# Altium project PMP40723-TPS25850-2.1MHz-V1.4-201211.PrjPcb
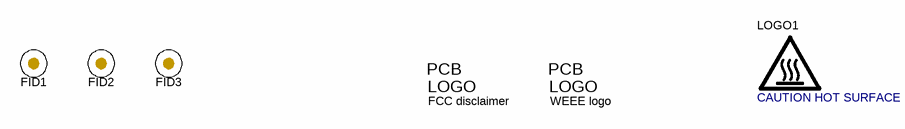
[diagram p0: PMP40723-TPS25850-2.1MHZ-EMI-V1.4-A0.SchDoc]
CopyrightYear: 2020; PCB_Layout: Pioneer Li; PCB_Rev: E1; PRJ_Customer: Public Release; PRJ_Engineer: Pioneer Li; PRJ_Number: PMP40723; PRJ_Title: Change in menu Project|Project Options|Parameters; SCH_Rev: E1; TechSupport: http://www.ti.com/support; TID: N/A
2 sheets, 79 parts. Net scope: global (net labels, ports and power ports of the same name join across sheets).
Board file: PMP40723-TPS25850-2.1MHZ-EMI-V1.4-A1.PcbDoc
Sheets:
  PMP40723-TPS25850-2.1MHZ-EMI-V1.4-A0.SchDoc
  PMP40723-TPS25850-2.1MHZ-EMI-V1.4-A1.SchDoc

## Sheet PMP40723-TPS25850-2.1MHZ-EMI-V1.4-A0.SchDoc
size 431 x 279 mm; Date: Not shown in title block; ApprovedBy: Not shown in title block; CheckedBy: Not shown in title block; Author: Not shown in title block; CompanyName: Not shown in title block; Engineer: Not shown in title block; Organization: Not shown in title block; Address1: Not shown in title block; Address2: Not shown in title block; Address3: Not shown in title block; Address4: Not shown in title block; DocumentNumber: 3; Revision: Use project parameter SCH_Rev; SheetNumber: 3; SheetTotal: 3; PageSetup: Record=PageOptions¦CenterHorizontal=True¦CenterVertical=True¦PrintScale=1.00¦XCorrection=1.00¦YCorrection=1.00¦PrintKind=0¦BorderSize=5000000¦LeftOffset=0¦BottomOffset=0¦Orientation=2¦PaperLength=1000¦PaperWidth=1000¦Scale=100¦PaperSource=15¦PrintQuality=600¦MediaType=1¦DitherType=10¦PaperKind=Letter¦PrintScaleMode=1

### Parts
FID1  Fiducial  [Fiducial10-20]  (value not drawn)
FID2  Fiducial  [Fiducial10-20]  (value not drawn)
FID3  Fiducial  [Fiducial10-20]  (value not drawn)
LOGO1  CAUTION HOT SURFACE  [IEC_HotSurface_Small]  (no BOM)
Logo3  FCC disclaimer  [FCC_disclaimer]  (no BOM)
Logo4  WEEE logo  [WEEE_Minimum]  (no BOM)

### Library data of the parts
FID1-FID3 = CMP-0077181-1: Fiducial mark.  There is nothing to buy or mount.
LOGO1 = CMP-0074837-1: IEC 61010-1 Hot Surface Warning; SymbolCreator: a0412235
Logo3 = CMP-0074847-1: FCC_disclaimer; Library Reference: Logo
Logo4 = CMP-0074769-1

## Sheet PMP40723-TPS25850-2.1MHZ-EMI-V1.4-A1.SchDoc
size 431 x 279 mm; Date: Not shown in title block; ApprovedBy: Not shown in title block; CheckedBy: Not shown in title block; Author: Not shown in title block; CompanyName: Not shown in title block; Engineer: Not shown in title block; Organization: Not shown in title block; Address1: Not shown in title block; Address2: Not shown in title block; Address3: Not shown in title block; Address4: Not shown in title block; DocumentNumber: 2; Revision: Use project parameter SCH_Rev; SheetNumber: 2; SheetTotal: 3; PageSetup: Record=PageOptions¦CenterHorizontal=True¦CenterVertical=True¦PrintScale=1.00¦XCorrection=1.00¦YCorrection=1.00¦PrintKind=0¦BorderSize=5000000¦LeftOffset=0¦BottomOffset=0¦Orientation=2¦PaperLength=1000¦PaperWidth=1000¦Scale=100¦PaperSource=15¦PrintQuality=600¦MediaType=1¦DitherType=10¦PaperKind=Letter¦PrintScaleMode=1
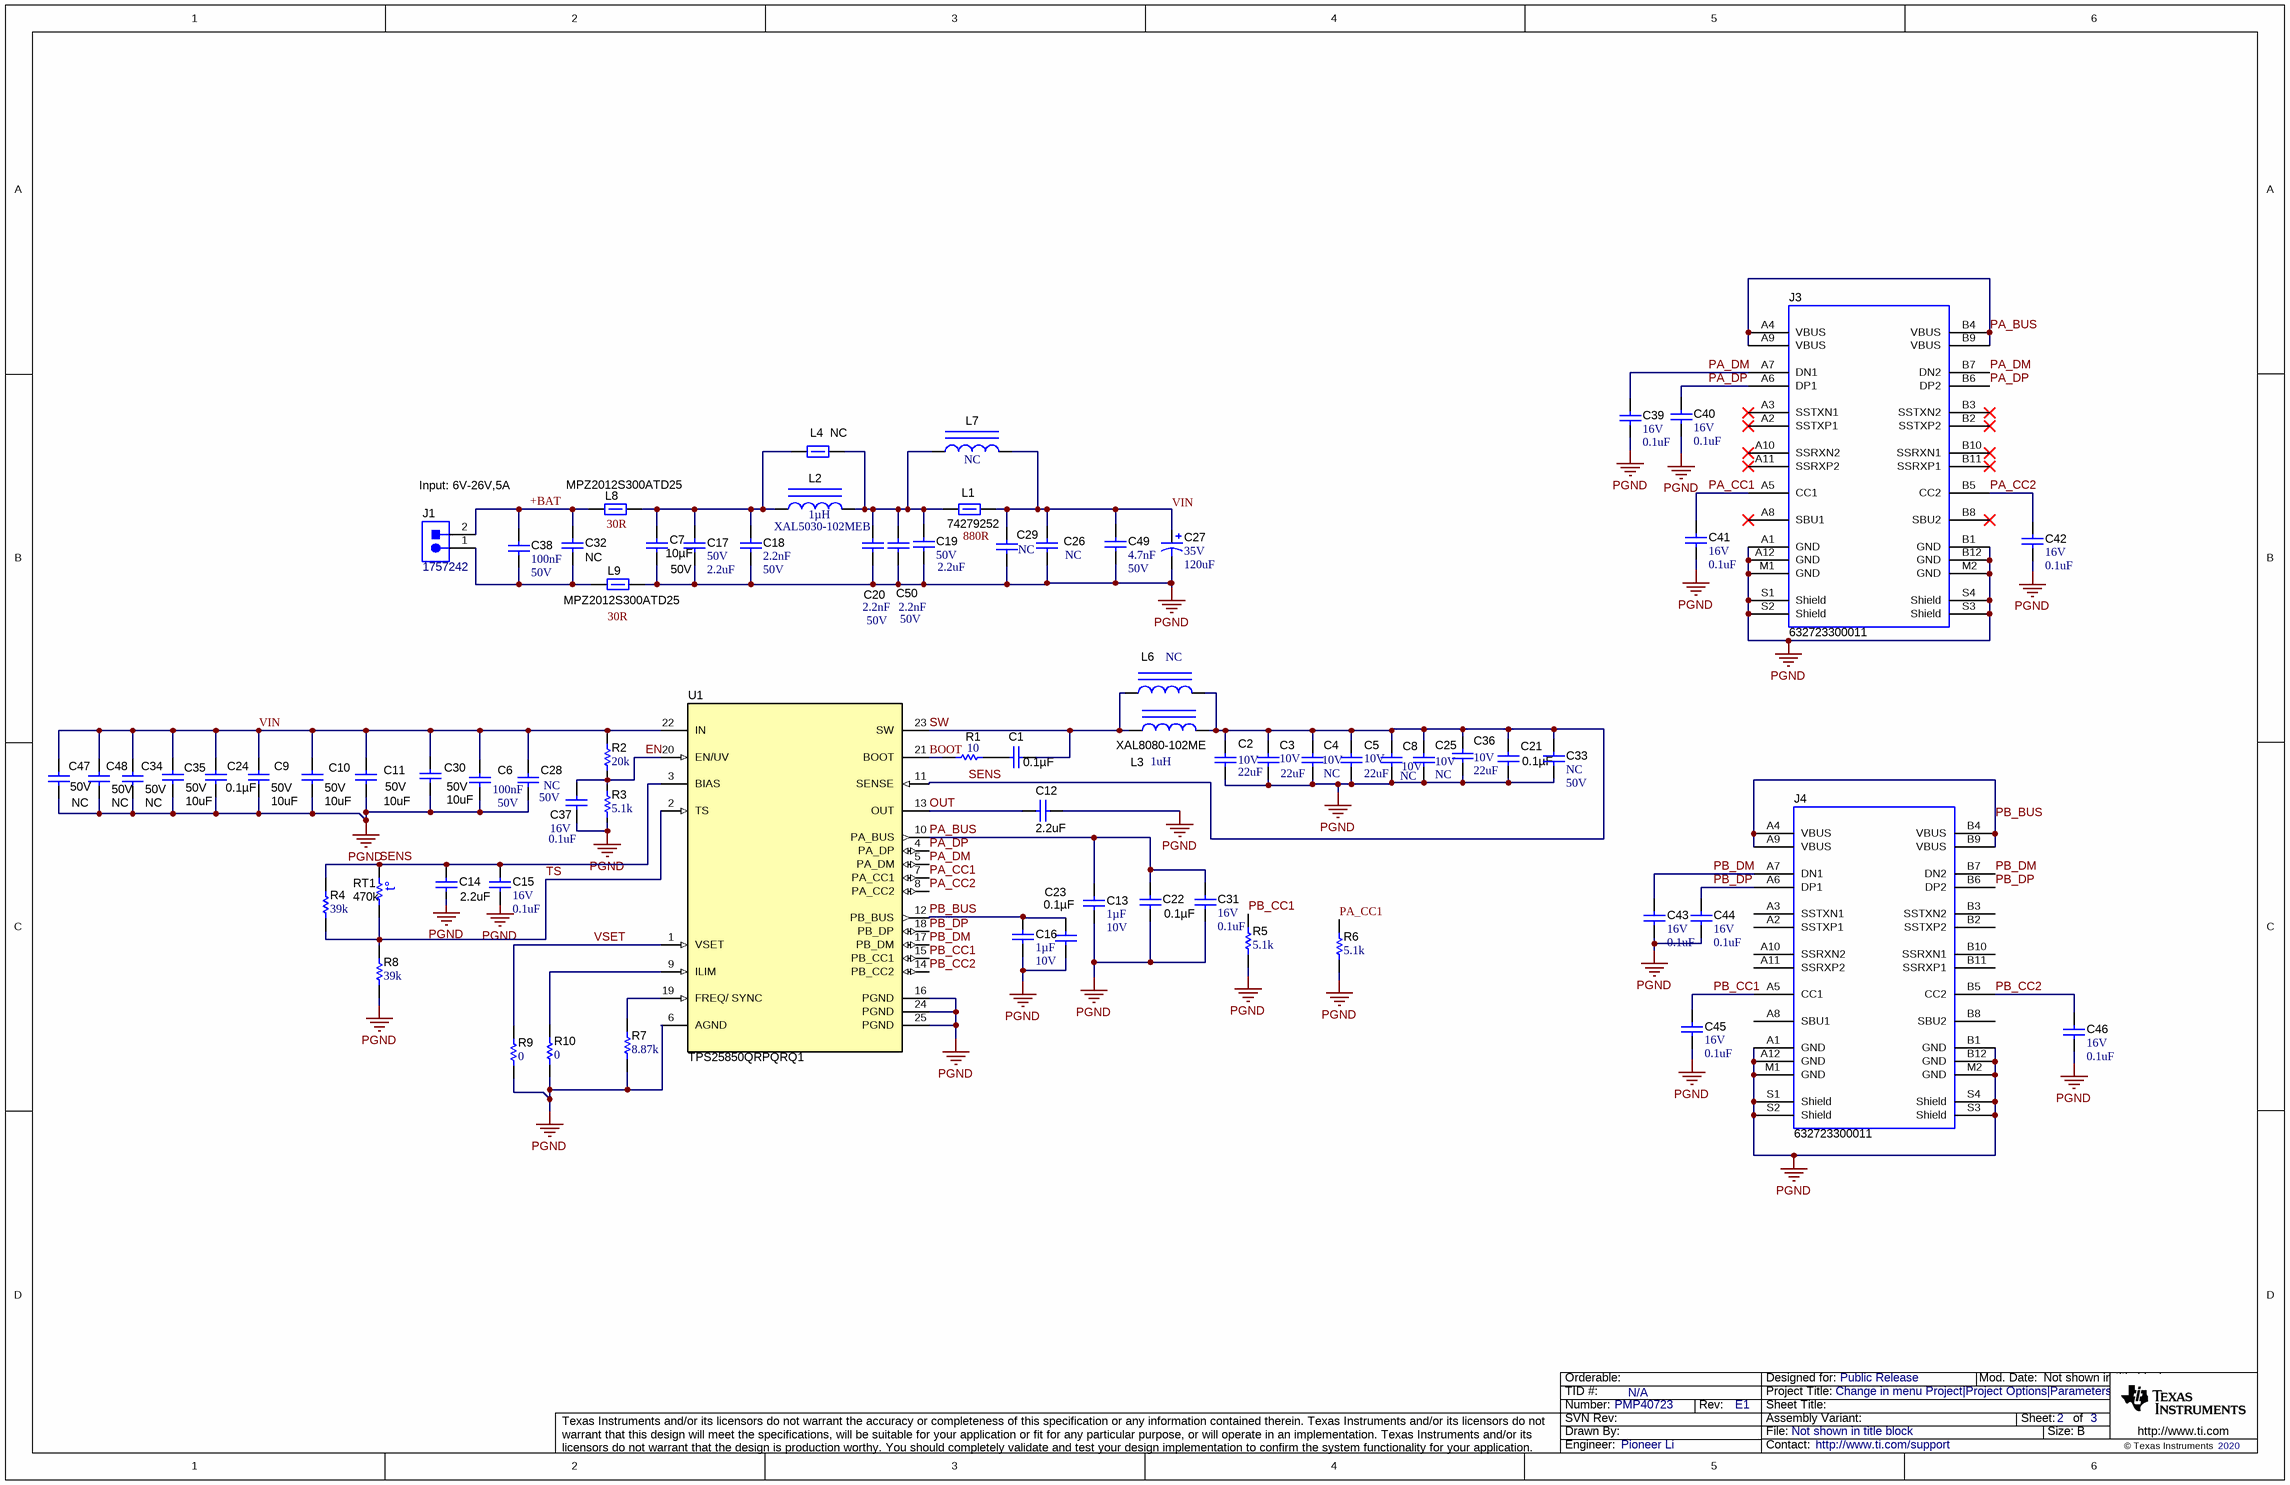
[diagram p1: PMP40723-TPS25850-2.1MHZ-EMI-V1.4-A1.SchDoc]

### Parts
C1  ValueDisplayed: 0.1µF  [0603]  (hidden comment: C0603C104K5RACAUTO)
C2  VDC_V: 10V  ValueDisplayed: 22uF  [1206_180]  (hidden comment: GRM31CR71A226ME15L)
C3  VDC_V: 10V  ValueDisplayed: 22uF  [1206_180]  (hidden comment: GRM31CR71A226ME15L)
C4  VDC_V: 10V  ValueDisplayed: NC  [1206_180]  (hidden comment: GRM31CR71A226ME15L)
C5  VDC_V: 10V  ValueDisplayed: 22uF  [1206_180]  (hidden comment: GRM31CR71A226ME15L)
C6  Cap_F: 100nF  VDC_V: 50V  [0805_HV]  (hidden comment: CL21B104MBCNNNC)
C7  ValueDisplayed: 10µF  VDC_V: 50V  [1206_190]  (hidden comment: CGA5L1X7R1H106K160AC)
C8  VDC_V: 10V  ValueDisplayed: NC  [1206_180]  (hidden comment: GRM31CR71A226ME15L)
C9  VDC_V: 50V  ValueDisplayed: 10uF  [1206_180]  (hidden comment: GRT31CR61H106KE01L)
C10  VDC_V: 50V  ValueDisplayed: 10uF  [1206_180]  (hidden comment: GRT31CR61H106KE01L)
C11  VDC_V: 50V  ValueDisplayed: 10uF  [1206_180]  (hidden comment: GRT31CR61H106KE01L)
C12  ValueDisplayed: 2.2uF  [0603]  (hidden comment: 885012106018)
C13  Cap_F: 1µF  VDC_V: 10V  [0805_HV]  (hidden comment: C2012X7R1A106M125AC)
C14  ValueDisplayed: 2.2uF  [0603]  (hidden comment: 885012106018)
C15  VDC_V: 16V  ValueDisplayed: 0.1uF  [0402]  (hidden comment: GRM155R71C104JA88D)
C16  Cap_F: 1µF  VDC_V: 10V  [0805_HV]  (hidden comment: C2012X7R1A106M125AC)
C17  VDC_V: 50V  ValueDisplayed: 2.2uF  [1206_180]  (hidden comment: GCM31CR71H225KA55L)
C18  Cap_F: 2.2nF  VDC_V: 50V  [0603]  (hidden comment: C0603C222K5RACTU)
C19  VDC_V: 50V  ValueDisplayed: 2.2uF  [1206_180]  (hidden comment: GCM31CR71H225KA55L)
C20  Cap_F: 2.2nF  VDC_V: 50V  [0603]  (hidden comment: C0603C222K5RACTU)
C21  ValueDisplayed: 0.1µF  [0603]  (hidden comment: C0603C104K5RACAUTO)
C22  ValueDisplayed: 0.1µF  [0603]  (hidden comment: C0603C104K5RACAUTO)
C23  ValueDisplayed: 0.1µF  [0603]  (hidden comment: C0603C104K5RACAUTO)
C24  ValueDisplayed: 0.1µF  [0603]  (hidden comment: C0603C104K5RACAUTO)
C25  VDC_V: 10V  ValueDisplayed: NC  [1206_180]  (hidden comment: GRM31CR71A226ME15L)
C26  ValueDisplayed: NC  [1206_190]  (hidden comment: CGA5L3X7R1H475K160AE)
C27  VDC_V: 35V  ValueDisplayed: 120uF  [SM_RADIAL_D8]  (hidden comment: EEHZKV121XUP)
C28  Cap_F: NC  VDC_V: 50V  [0805_HV]  (hidden comment: CL21B104MBCNNNC)
C29  GRM188R71H332KA01D  [0603]  (value not drawn)
C30  VDC_V: 50V  ValueDisplayed: 10uF  [1206_180]  (hidden comment: GRT31CR61H106KE01L)
C31  VDC_V: 16V  ValueDisplayed: 0.1uF  [0402]  (hidden comment: GRM155R71C104JA88D)
C32  ValueDisplayed: NC  [0603]  (hidden comment: C0603C104K5RACAUTO)
C33  Cap_F: NC  VDC_V: 50V  [0603]  (hidden comment: C0603X222K5RACTU)
C34  VDC_V: 50V  ValueDisplayed: NC  [1206_180]  (hidden comment: GRT31CR61H106KE01L)
C35  VDC_V: 50V  ValueDisplayed: 10uF  [1206_180]  (hidden comment: GRT31CR61H106KE01L)
C36  VDC_V: 10V  ValueDisplayed: 22uF  [1206_180]  (hidden comment: GRM31CR71A226ME15L)
C37  VDC_V: 16V  ValueDisplayed: 0.1uF  [0402]  (hidden comment: C0402C104K4RACAUTO)
C38  Cap_F: 100nF  VDC_V: 50V  [0805_150]  (hidden comment: CEU4J2X7R1H104K125AE)
C39  VDC_V: 16V  ValueDisplayed: 0.1uF  [0402]  (hidden comment: GRM155R71C104JA88D)
C40  VDC_V: 16V  ValueDisplayed: 0.1uF  [0402]  (hidden comment: GRM155R71C104JA88D)
C41  VDC_V: 16V  ValueDisplayed: 0.1uF  [0402]  (hidden comment: GRM155R71C104JA88D)
C42  VDC_V: 16V  ValueDisplayed: 0.1uF  [0402]  (hidden comment: GRM155R71C104JA88D)
C43  VDC_V: 16V  ValueDisplayed: 0.1uF  [0402]  (hidden comment: GRM155R71C104JA88D)
C44  VDC_V: 16V  ValueDisplayed: 0.1uF  [0402]  (hidden comment: GRM155R71C104JA88D)
C45  VDC_V: 16V  ValueDisplayed: 0.1uF  [0402]  (hidden comment: GRM155R71C104JA88D)
C46  VDC_V: 16V  ValueDisplayed: 0.1uF  [0402]  (hidden comment: GRM155R71C104JA88D)
C47  VDC_V: 50V  ValueDisplayed: NC  [1206_180]  (hidden comment: GRT31CR61H106KE01L)
C48  VDC_V: 50V  ValueDisplayed: NC  [1206_180]  (hidden comment: GRT31CR61H106KE01L)
C49  Cap_F: 4.7nF  VDC_V: 50V  [0603]  (hidden comment: GCM188R71H472KA37D)
C50  Cap_F: 2.2nF  VDC_V: 50V  [0603]  (hidden comment: C0603C222K5RACTU)
J1  1757242  [PHOENIX_1757242]
J3  632723300011  [Wurth_632_723_300_011]
J4  632723300011  [Wurth_632_723_300_011]
L1  74279252  [1812_170_HighSpeed]
L2  ValueDisplayed: 1µH  [XAL5030]  (hidden comment: XAL5030-102MEB)
L3  XAL8080-102ME  ValueDisplayed: NC  [XAL8080]
L4  NC  [1812_170_HighSpeed]
L6  ValueDisplayed: 1uH  [XAL6060]  (hidden comment: XAL6060-472MEB)
L7  PartNumber: NC  [XAL5030]  (hidden comment: XAL5030-102MEB)
L8  MPZ2012S300ATD25  [1206]
L9  MPZ2012S300ATD25  [1206]
R1  ValueDisplayed: 10  [0603]  (hidden comment: CRCW060310R0JNEA)
R2  ValueDisplayed: 20k  [0402]  (hidden comment: CRCW040220K0JNED)
R3  ValueDisplayed: 5.1k  [0402]  (hidden comment: CRCW04025K10JNED)
R4  ValueDisplayed: 39k  [0402]  (hidden comment: ERJ-2GEJ393X)
R5  ValueDisplayed: 5.1k  [0402]  (hidden comment: CRCW04025K10JNED)
R6  ValueDisplayed: 5.1k  [0402]  (hidden comment: CRCW04025K10JNED)
R7  ValueDisplayed: 8.87k  [0402]  (hidden comment: CRCW04028K87FKED)
R8  ValueDisplayed: 39k  [0402]  (hidden comment: ERJ-2GEJ393X)
R9  ValueDisplayed: 0  [0402]  (hidden comment: MCR01MZPJ000)
R10  ValueDisplayed: 0  [0402]  (hidden comment: MCR01MZPJ000)
RT1  value 470k  [0603S]  (hidden comment: NCP18WM474J03RB)
U1  TPS25850QRPQRQ1  [RPQ0025A]

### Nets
PGND: C2.2 C3.2 C4.2 C5.2 C6.2 C7.2 C8.2 C9.2 C10.2 C11.2 C12.2 C13.2 C14.2 C15.2 C16.2 C17.2 C18.2 C19.2 C20.2 C21.2 C22.2 C23.2 C24.2 C25.2 C26.2 C27.2(-) C28.2 C29.2 C30.2 C31.2 C33.2 C34.2 C35.2 C36.2 C37.2 C39.2 C40.2 C41.2 C42.2 C43.2 C44.2 C45.2 C46.2 C47.2 C48.2 C49.2 C50.2 J3.A1(GND) J3.A12(GND) J3.B1(GND) J3.B12(GND) J3.M1(GND) J3.M2(GND) J3.S1(Shield) J3.S2(Shield) J3.S3(Shield) J3.S4(Shield) J4.A1(GND) J4.A12(GND) J4.B1(GND) J4.B12(GND) J4.M1(GND) J4.M2(GND) J4.S1(Shield) J4.S2(Shield) J4.S3(Shield) J4.S4(Shield) L9.2 R3.1 R5.1 R6.1 R7.1 R8.1 R9.1 R10.1 U1.6(AGND) U1.16(PGND) U1.24(PGND) U1.25(PGND)
+BAT: C32.1 C38.1 J1.2 L8.1
BOOT: R1.1 U1.21(BOOT)
EN: C37.1 R2.1 R3.2 U1.20(EN/UV)
OUT: C12.1 U1.13(OUT)
PA_BUS: C13.1 C22.1 C31.1 J3.A4(VBUS) J3.A9(VBUS) J3.B4(VBUS) J3.B9(VBUS) U1.10(PA_BUS)
PA_CC1: C41.1 J3.A5(CC1) R6.2 U1.7(PA_CC1)
PA_CC2: C42.1 J3.B5(CC2) U1.8(PA_CC2)
PA_DM: C39.1 J3.A7(DN1) J3.B7(DN2) U1.5(PA_DM)
PA_DP: C40.1 J3.A6(DP1) J3.B6(DP2) U1.4(PA_DP)
PB_BUS: C16.1 C23.1 J4.A4(VBUS) J4.A9(VBUS) J4.B4(VBUS) J4.B9(VBUS) U1.12(PB_BUS)
PB_CC1: C45.1 J4.A5(CC1) R5.2 U1.15(PB_CC1)
PB_CC2: C46.1 J4.B5(CC2) U1.14(PB_CC2)
PB_DM: C43.1 J4.A7(DN1) J4.B7(DN2) U1.17(PB_DM)
PB_DP: C44.1 J4.A6(DP1) J4.B6(DP2) U1.18(PB_DP)
SENS: C2.1 C3.1 C4.1 C5.1 C8.1 C14.1 C15.1 C21.1 C25.1 C33.1 C36.1 L3.2 L6.2 R4.2 RT1.2 U1.3(BIAS) U1.11(SENSE)
SW: C1.1 L3.1 L6.1 U1.23(SW)
TS: R4.1 R8.2 RT1.1 U1.2(TS)
VIN: C6.1 C9.1 C10.1 C11.1 C24.1 C26.1 C27.1(+) C28.1 C29.1 C30.1 C34.1 C35.1 C47.1 C48.1 C49.1 L1.2 L7.2 R2.2 U1.22(IN)
VSET: R9.2 U1.1(VSET)
NetC1_2: C1.2 R1.2
NetC7_1: C7.1 C17.1 C18.1 L2.1 L4.1 L8.2
NetC19_1: C19.1 C20.1 C50.1 L1.1 L2.2 L4.2 L7.1
NetC32_2: C32.2 C38.2 J1.1 L9.1
NetR7_2: R7.2 U1.19(FREQ/_SYNC)
NetR10_2: R10.2 U1.9(ILIM)

Not connected (* = marked no-connect by the designer): J3 A2(SSTXP1)* A3(SSTXN1)* A8(SBU1)* A10(SSRXN2)* A11(SSRXP2)* B2(SSTXP2)* B3(SSTXN2)* B8(SBU2)* B10(SSRXN1)* B11(SSRXP1)*; J4 A2(SSTXP1) A3(SSTXN1) A8(SBU1) A10(SSRXN2) A11(SSRXP2) B2(SSTXP2) B3(SSTXN2) B8(SBU2) B10(SSRXN1) B11(SSRXP1)

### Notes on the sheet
- Input: 6V-26V,5A
- Labels drawn without touching a wire or pin: 30R, 880R, FREQ, ILIM

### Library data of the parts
C1 C21-C24 C32 = CMP-0079602-1: CAP, CERM, 0.1 µF, 50 V,+/- 10%, X7R, AEC-Q200 Grade 1, 0603; Manufacturer: Kemet; TaMin_C: -55°C; Polarized: N; SizeAreaWB_mm2: 4.68; U/M: EA; Value: 0.1uF; TaMax_C: 125°C; SizeZ_mm: 1; SizeX_mm: 1.6; SizeY_mm: 0.8; Value2: 50V; SizeArea_mm2: 1.28; CompType: Capacitor; AEC Qualified: Y; Cap_F: 100nF; AEC Category: Q200
C2-C5 C8 C25 C36 = CMP-0008960-2: CAP, CERM, 22 uF, 10 V, +/- 20%, X7R, 1206; Manufacturer: MuRata; TaMin_C: -55°C; Polarized: N; SizeAreaWB_mm2: 10.92; Value1: Unknown; U/M: EA; Value: 22uF; TaMax_C: 125°C; SizeZ_mm: 1.8; SizeX_mm: 3.2; SizeY_mm: 1.6; Cap_Case: 1206; SizeArea_mm2: 5.12; Cap_F: 22µF; AEC Category: Q200
C6 C28 = CMP-0082524-1: CAP, CERM, 0.1 µF, 50 V,+/- 20%, X7R, 0805; Manufacturer: Samsung; SizeAreaWB_mm2: 6.75; SizeArea_mm2: 2.5; AEC Qualified: N; AEC Category: Q200; Value: 0.1uF; TaMax_C: 125°C; SizeZ_mm: 1.45; TaMin_C: -55°C; SizeY_mm: 1.25; U/M: EA; SizeX_mm: 2; Cap_Case: 0805; ValueDisplayed: 0.1µF
C7 = CMP-0085950-1: CAP, CERM, 10 µF, 50 V,+/- 10%, X7R, AEC-Q200 Grade 1, 1206; Manufacturer: TDK; SizeZ_mm: 1.9; Value: 10uF; Cap_Case: 1206; AEC Grade: 1; TaMin_C: -55°C; U/M: EA; SizeArea_mm2: 5.12; TaMax_C: 125°C; AEC Qualified: Y; AEC Category: Q200; SizeX_mm: 3.2; SizeY_mm: 1.6; Polarized: N; SizeAreaWB_mm2: 10.92
C9-C11 C30 C34 C35 C47 C48 = CMP-0009015-1: CAP, CERM, 10 uF, 50 V, +/- 10%, X5R, AEC-Q200 Grade 1, 1206; Manufacturer: MuRata; TaMin_C: -55°C; Polarized: N; SizeAreaWB_mm2: 10.92; Value1: Unknown; U/M: EA; Value: 10uF; TaMax_C: 85°C; SizeZ_mm: 1.8; SizeX_mm: 3.2; SizeY_mm: 1.6; Cap_Case: 1206; SizeArea_mm2: 5.12; AEC Qualified: Y; Cap_F: 10µF; AEC Grade: 1; AEC Category: Q200
C12 C14 = CMP-0006825-5: CAP, CERM, 2.2 uF, 16 V, +/- 20%, X5R, 0603; Manufacturer: Wurth Elektronik; TaMin_C: -55°C; Polarized: N; SizeAreaWB_mm2: 4.68; Value1: Unknown; U/M: EA; Value: 2.2uF; TaMax_C: 85°C; SizeZ_mm: 1; SizeX_mm: 1.6; SizeY_mm: 0.8; Value2: 16V; SizeArea_mm2: 1.28; CompType: Capacitor; Cap_F: 2.2µF; AEC Category: Q200
C13 C16 = CMP-0007864-2: CAP, CERM, 10 uF, 10 V, +/- 20%, X7R, 0805; Manufacturer: TDK; TaMin_C: -55°C; Polarized: N; SizeAreaWB_mm2: 6.75; Value1: Unknown; U/M: EA; Value: 10uF; TaMax_C: 125°C; SizeZ_mm: 1.45; SizeX_mm: 2; SizeY_mm: 1.25; Cap_Case: 0805; SizeArea_mm2: 2.5; AEC Category: Q200
C15 C31 C39-C46 = CMP-0006640-2: CAP, CERM, 0.1 uF, 16 V, +/- 5%, X7R, 0402; Manufacturer: MuRata; TaMin_C: -55°C; Polarized: N; SizeAreaWB_mm2: 3; Value1: Unknown; U/M: EA; Value: 0.1uF; TaMax_C: 125°C; SizeZ_mm: 0.6; SizeX_mm: 1; SizeY_mm: 0.5; Cap_F: 100nF; AEC Category: Q200
C17 C19 = CMP-0008814-2: CAP, CERM, 2.2 uF, 50 V, +/- 10%, X7R, AEC-Q200 Grade 1, 1206; Manufacturer: MuRata; TaMin_C: -55°C; Polarized: N; SizeAreaWB_mm2: 10.92; Value1: Unknown; U/M: EA; Value: 2.2uF; TaMax_C: 125°C; SizeZ_mm: 1.8; SizeX_mm: 3.2; SizeY_mm: 1.6; Cap_Case: 1206; SizeArea_mm2: 5.12; AEC Qualified: Y; Cap_F: 2.2µF; AEC Grade: 1; AEC Category: Q200
C18 C20 C50 = CMP-0006898-4: CAP, CERM, 2200 pF, 50 V, +/- 10%, X7R, 0603; Manufacturer: Kemet; TaMin_C: -55°C; Polarized: N; SizeAreaWB_mm2: 4.68; Value1: Unknown; U/M: EA; Value: 2200pF; TaMax_C: 125°C; SizeZ_mm: 1; SizeX_mm: 1.6; SizeY_mm: 0.8; SizeArea_mm2: 1.28; AEC Category: Q200
C26 = CMP-0085349-1: CAP, CERM, 4.7 µF, 50 V,+/- 10%, X7R, AEC-Q200 Grade 1, 1206; Manufacturer: TDK; Cap_Case: 1206; Value2: 50V; AEC Category: Q200; SizeY_mm: 1.6; TaMin_C: -55°C; TaMax_C: 125°C; U/M: EA; AEC Qualified: Y; SizeAreaWB_mm2: 10.92; Cap_F: 4.7µF; AEC Grade: 1; SizeZ_mm: 1.9; SizeArea_mm2: 5.12; Value: 4.7uF; Polarized: N; SizeX_mm: 3.2
C27 = CMP-0010724-1: CAP, AL, 120 uF, 35 V, +/- 20%, 0.035 ohm, AEC-Q200 , SMD; Manufacturer: Panasonic; TaMin_C: -55°C; ESR_ohm: 0.035; Polarized: Y; SizeAreaWB_mm2: 84.28; Value: 120uF; TaMax_C: 125°C; SizeZ_mm: 7.7; SizeX_mm: 7.8; SizeY_mm: 6.6; Cap_Case: D8; SizeArea_mm2: 51.48; CompType: Capacitor; IRMS_A: 1.7A; AEC Category: Q200
C29 = CMP-0007450-4: CAP, CERM, 3300 pF, 50 V, +/- 10%, X7R, 0603; Manufacturer: MuRata; TaMin_C: -55°C; Polarized: N; SizeAreaWB_mm2: 4.68; Value1: Unknown; U/M: EA; Value: 3300pF; TaMax_C: 125°C; SizeZ_mm: 1; SizeX_mm: 1.6; SizeY_mm: 0.8; Value2: 50V; SizeArea_mm2: 1.28; Cap_F: 3.3nF; AEC Category: Q200
C33 = CMP-0006983-4: CAP, CERM, 2200 pF, 50 V, +/- 10%, X7R, 0603; Manufacturer: Kemet; TaMin_C: -55°C; Polarized: N; SizeAreaWB_mm2: 4.68; Value1: Unknown; U/M: EA; Value: 2200pF; TaMax_C: 125°C; SizeZ_mm: 1; SizeX_mm: 1.6; SizeY_mm: 0.8; SizeArea_mm2: 1.28; AEC Category: Q200
C37 = CMP-0006237-2: CAP, CERM, 0.1 uF, 16 V, +/- 10%, X7R, AEC-Q200 Grade 1, 0402; Manufacturer: Kemet; TaMin_C: -55°C; Polarized: N; SizeAreaWB_mm2: 3; Value1: Unknown; U/M: EA; Value: 0.1uF; TaMax_C: 125°C; SizeZ_mm: 0.6; SizeX_mm: 1; SizeY_mm: 0.5; AEC Qualified: Y; Cap_F: 100nF; AEC Category: Q200
C38 = CMP-0007961-2: CAP, CERM, 0.1 uF, 50 V, +/- 10%, X7R, AEC-Q200 Grade 1, 0805; Manufacturer: TDK; TaMin_C: -55°C; Polarized: N; SizeAreaWB_mm2: 6.75; Value1: Unknown; U/M: EA; Value: 0.1uF; TaMax_C: 125°C; SizeZ_mm: 1.5; SizeX_mm: 2; SizeY_mm: 1.25; Cap_Case: 0805; SizeArea_mm2: 2.5; AEC Qualified: Y; AEC Grade: 1; AEC Category: Q200
C49 = CMP-0007146-4: CAP, CERM, 4700 pF, 50 V, +/- 10%, X7R, AEC-Q200 Grade 1, 0603; Manufacturer: MuRata; TaMin_C: -55°C; Polarized: N; SizeAreaWB_mm2: 4.68; Value1: Unknown; U/M: EA; Value: 4700pF; TaMax_C: 125°C; SizeZ_mm: 1; SizeX_mm: 1.6; SizeY_mm: 0.8; SizeArea_mm2: 1.28; AEC Qualified: Y; AEC Category: Q200
J1 = CMP-0055534-1: Header (Shrouded), 5.08 mm, 2x1, Tin, R/A, TH; Manufacturer: Phoenix Contact; CT: FALSE
J3 J4 = CMP-0080891-1: Connector, Receptacle, USB Type C, R/A; Manufacturer: Wurth Elektronik; Current_A: 3A; Gender: Female; Voltage_V: 5V; ContactFinish: Gold; Cert_UL: Y
L1 = CMP-0003170-1: Ferrite Bead, 880 ohm @ 100 MHz, 4 A, 1812; Manufacturer: Wurth Elektronik; Ztyp@1GHz_Ohm: 80.561; ZTyp@100MHz_Ohm: 880; SizeAreaWB_mm2: 23.1; DCR_ohm: 0.035; Value1: 0.035 ohm; Value: 880 ohm; Imax_A: 4A; SizeZ_mm: 1.7; SizeX_mm: 4.5; SizeY_mm: 3.2; SizeArea_mm2: 14.4
L2 = CMP-0082088-1: Inductor, Shielded, CAPPR7.5-16X20, 1 µH, 11.1 A, 0.0094 ohm, AEC-Q200 Grade 1, SMD; Manufacturer: Coilcraft; Isat: 14A @ 30% inductance drop; Irms: 11.1A @ 40C rise; SizeAreaWB_mm2: 54.4544; DCR_ohm: 9.4m; Value: 1uH; Imax_A: 11.1A; SizeZ_mm: 3.1; SizeX_mm: 5.28; SizeY_mm: 5.48; SizeArea_mm2: 28.9344; AEC Qualified: Y; AEC Grade: 1; AEC Category: Q200
L3 = CMP-0061062-1: Inductor, Shielded, Composite, 4.7 uH, 10.5 A, 0.00889 ohm, SMD; Manufacturer: Coilcraft; PartNumber: XAL8080-472ME; Isat: 17.4A @ 20% inductance drop; Irms: 10.5A @ 20C rise; Green_Lifecycle: Not Set; SizeAreaWB_mm2: 107.06; DCR_ohm: 8.89m; Green_REACh: Incomplete; Value: 4.7uH; Imax_A: 10.5A; SizeZ_mm: 8; SizeX_mm: 8.1; SizeY_mm: 8.6; SizeArea_mm2: 69.66; Ind_H: 4.7µH; AEC Category: Q200
L4 = CMP-0003170-1: Ferrite Bead, 880 ohm @ 100 MHz, 4 A, 1812; Manufacturer: Wurth Elektronik; PartNumber: 74279252; Ztyp@1GHz_Ohm: 80.561; ZTyp@100MHz_Ohm: 880; SizeAreaWB_mm2: 23.1; DCR_ohm: 0.035; Value1: 0.035 ohm; Value: 880 ohm; Imax_A: 4A; SizeZ_mm: 1.7; SizeX_mm: 4.5; SizeY_mm: 3.2; SizeArea_mm2: 14.4
L6 = CMP-0061020-2: Inductor, Shielded, Composite, 4.7 µH, 10.5 A, 0.0144 ohm, AEC-Q200 Grade 1, SMD; Manufacturer: Coilcraft; SizeZ_mm: 6.1; Ind_H: 4.7µH; AEC Qualified: Y; Imax_A: 10.5A; Value: 4.7uH; SizeY_mm: 6.56; AEC Category: Q200; SizeAreaWB_mm2: 71.5616; Green_REACh: Incomplete; DCR_ohm: 0.0144; Isat: 10.5A @ 30% inductance drop; Green_Lifecycle: Not Set; SizeX_mm: 6.36; SizeArea_mm2: 41.7216; AEC Grade: 1; Irms: 12.3A @ 40C rise
L7 = CMP-0082088-1: Inductor, Shielded, CAPPR7.5-16X20, 1 µH, 11.1 A, 0.0094 ohm, AEC-Q200 Grade 1, SMD; Manufacturer: Coilcraft; Isat: 14A @ 30% inductance drop; Irms: 11.1A @ 40C rise; SizeAreaWB_mm2: 54.4544; DCR_ohm: 9.4m; Value: 1uH; Imax_A: 11.1A; SizeZ_mm: 3.1; SizeX_mm: 5.28; SizeY_mm: 5.48; SizeArea_mm2: 28.9344; Ind_H: 1µH; AEC Qualified: Y; AEC Grade: 1; AEC Category: Q200
L8 L9 = CMP-0003139-1: Ferrite Bead, 30ohm @ 100 MHz, 6 A, 0805; Manufacturer: TDK; ZTyp@100MHz_Ohm: 30; DCR_ohm: 10 m; Value1: 0.010 ohm; Imax_A: 6A; SizeZ_mm: 0.85; SizeX_mm: 2.0; SizeY_mm: 1.25
R1 = CMP-0025703-4: RES, 10, 5%, 0.1 W, AEC-Q200 Grade 0, 0603; Manufacturer: Vishay-Dale; Power_W: 100mW; TempCo: 200 ppm/C; Value_Code: 10R0; Value: 10; EIA_Code: E24; SizeX_mm: 1.6; SizeY_mm: 0.8; SizeZ_mm: 1; Value2: 0.1W; SizeArea_mm2: 1.28; AEC Qualified: Y; VDC_V: 75V; AEC Category: Q200; AEC Grade: 0
R2 = CMP-0026875-3: RES, 20 k, 5%, 0.063 W, AEC-Q200 Grade 0, 0402; Manufacturer: Vishay-Dale; Power_W: 63mW; TempCo: 200 ppm/C; Value_Code: 20k0; Value: 20k; EIA_Code: E24; SizeX_mm: 1; SizeY_mm: 0.5; SizeZ_mm: 0.6; Value2: 0.063W; AEC Qualified: Y; VDC_V: 50V; AEC Category: Q200; AEC Grade: 0
R3 R5 R6 = CMP-0026951-5: RES, 5.1 k, 5%, 0.063 W, AEC-Q200 Grade 0, 0402; Manufacturer: Vishay-Dale; Power_W: 63mW; TempCo: 200 ppm/C; Value_Code: 5k10; Value: 5.1k; EIA_Code: E24; SizeX_mm: 1; SizeY_mm: 0.5; SizeZ_mm: 0.6; Value2: 0.063W; AEC Qualified: Y; VDC_V: 50V; AEC Category: Q200; AEC Grade: 0
R4 R8 = CMP-0026998-2: RES, 39 k, 5%, 0.1 W, AEC-Q200 Grade 0, 0402; Manufacturer: Panasonic; Power_W: 100mW; TempCo: 200 ppm/C; Value_Code: 39k0; U/M: EA; Value: 39k; EIA_Code: E24; SizeX_mm: 1; SizeY_mm: 0.5; SizeZ_mm: 0.6; Value2: 0.1W; AEC Qualified: Y; VDC_V: 50V; AEC Grade: 0; AEC Category: Q200
R7 = CMP-0026592-2: RES, 8.87 k, 1%, 0.063 W, AEC-Q200 Grade 0, 0402; Manufacturer: Vishay-Dale; Power_W: 63mW; TempCo: 100 ppm/C; Value_Code: 8k87; Value: 8.87k; EIA_Code: E96; SizeX_mm: 1; SizeY_mm: 0.5; SizeZ_mm: 0.6; Value2: 0.063W; AEC Qualified: Y; VDC_V: 50V; AEC Category: Q200; AEC Grade: 0
R9 R10 = CMP-0027002-2: RES, 0, 5%, 0.063 W, 0402; Manufacturer: Rohm; Power_W: 63mW; TempCo: 500 ppm/C; Value_Code: 0000; U/M: EA; Value: 0; EIA_Code: E24; SizeX_mm: 1; SizeY_mm: 0.5; SizeZ_mm: 0.6; Value2: 0.063W; VDC_V: 50V; AEC Category: Q200
RT1 = CMP-0002545-3: Thermistor NTC, 470k ohm, 5%, 0603; Manufacturer: MuRata; TaMax_C: 125°C; SizeX_mm: 1.6; SizeY_mm: 0.8; TaMin_C: -40°C; Power_W: 100mW; SizeZ_mm: 1; SizeArea_mm2: 1.28; SizeAreaWB_mm2: 4.68; U/M: EA
U1 = CMP-0860365-2: Dual 3A USB Type-C Charging Ports Controller with Programmable Current Limit and Thermal Management, RPQ0025A (VQFN-25); Alternate Manufacturer: Texas Instruments; SizeZ_mm: 1; SizeX_mm: 3.5; AEC Category: Q200; CompType: IC; SizeY_mm: 4.5; SizeArea_mm2: 15.75; AEC Qualified: Y; SizeAreaWB_mm2: 24.75

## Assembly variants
001: not fitted C4 C8 C25 C26 C28 C29 C32 C33 C34 C47 C48 C50 L4 L6 L7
